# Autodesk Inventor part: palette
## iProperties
Shininess: 64.0
Length Units: 11269
Angle Units: 11279
Time Units: 11290
Mass Units: 11283
Length Display Precision: 3
Angle Display Precision: 2
Compacted: True
Part Number: palette
Document SubType Name: Modeling
Created: 2005-01
Material: Par défaut
Designer: Flavien MARTY
Density: 0.0
Volumn: 0.0
Area: 0.0
PropertySet Name: Model Information
Control State: 0
Master: False
Checked Out: False
Norme de conversion: STEP AP203
Nom du fichier: Palette pièce.STEP
Préprocesseur: SolidWorks 2001039
Postprocesseur: Build: Release: 6 RTM Build: 90b - Date: Tue 09/24/2002
Unités envoyées: MILLIMETERS
Incertitude: 0.0
Author: Flavien MARTY
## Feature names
1. Base1
